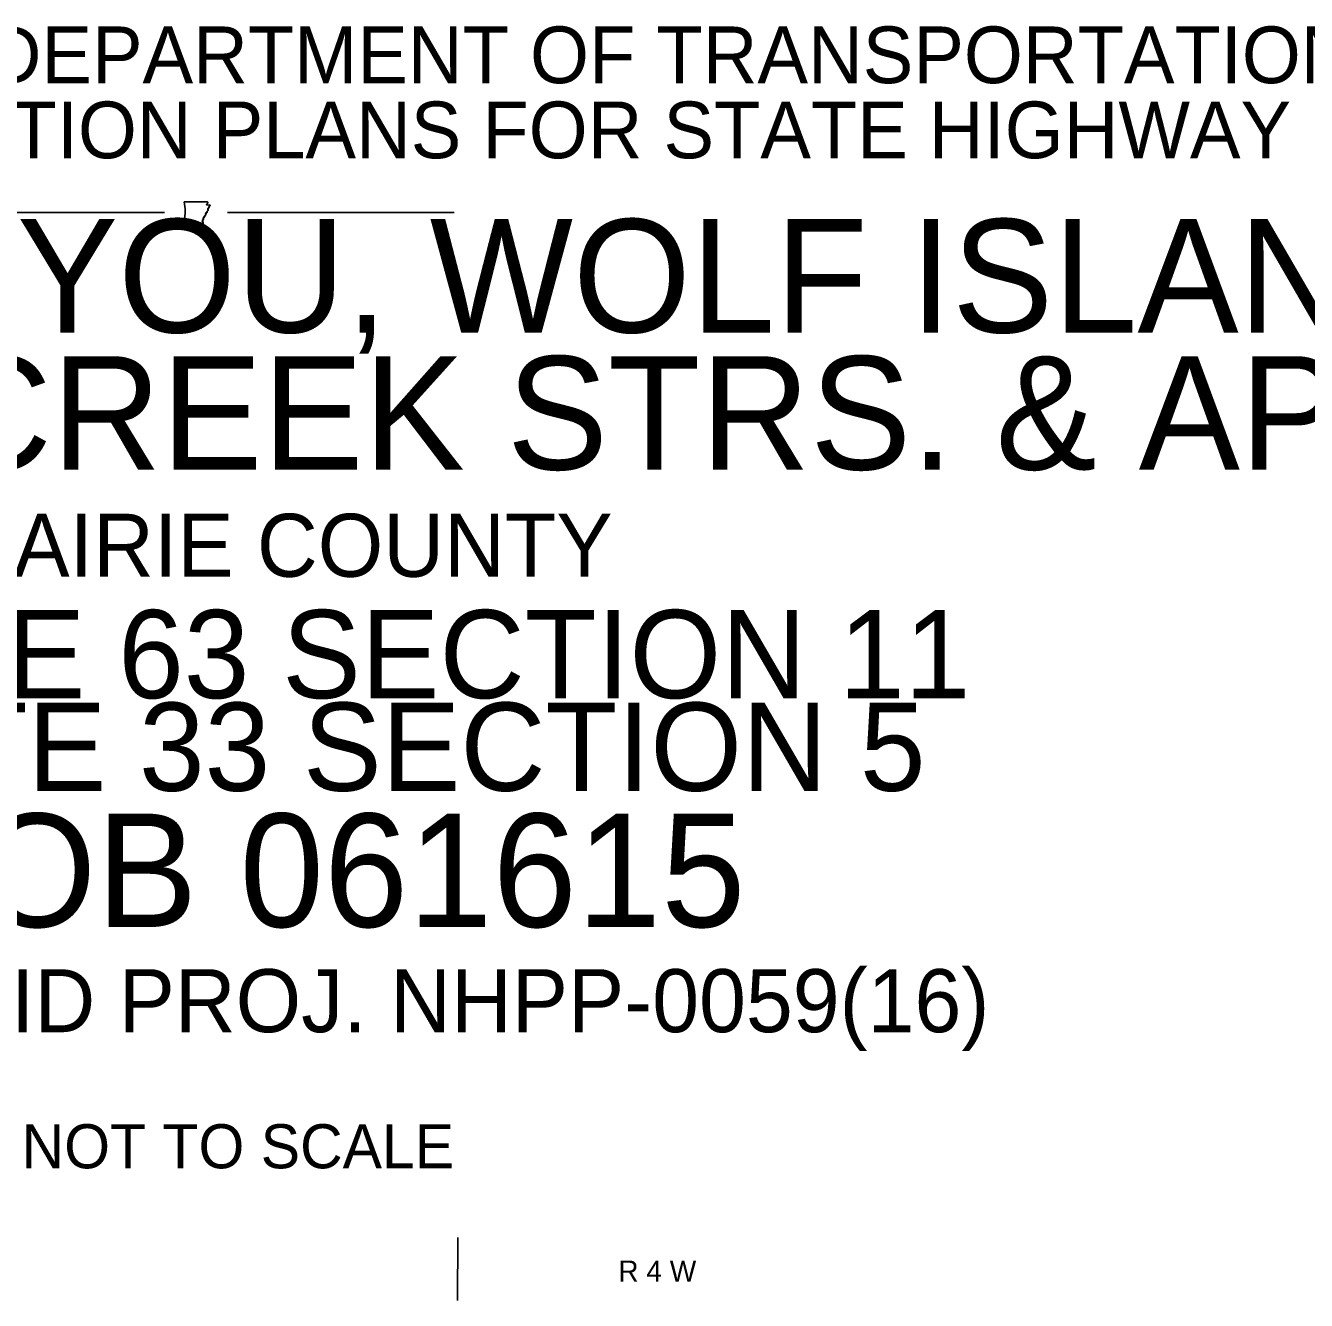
# Model space of a CAD drawing. Extents: x 982240 to 1103002, y 974866 to 1054902.
# Drawn here: x 1037189 to 1073786, y 1018200 to 1054617 of the extents above; entities that cross this region are included whole.
import ezdxf

# ---------------------------------------------------------------- set-up
doc = ezdxf.new("R2010")
doc.units = 0
doc.layers.add('R_Dimension', color=7, linetype='Continuous')
doc.layers.add('R_Draft', color=7, linetype='Continuous')

msp = doc.modelspace()

# ---------------------------------------------------------------- linework, layer by layer
at = {"layer": 'R_Dimension'}
msp.add_line((1049543, 1019999), (1049530, 1018200), dxfattribs=at)
at = {"layer": 'R_Draft'}
for p, q in [((1034676, 1049282), (1041156, 1049282)), ((1042956, 1049282), (1049436, 1049282))]:
    msp.add_line(p, q, dxfattribs=at)
for points in [[(1041720, 1049582), (1041917, 1049582), (1042089, 1049582), (1042293, 1049585), (1042387, 1049587)], [(1041735, 1049050), (1041745, 1049380), (1041720, 1049582)], [(1042358, 1049492), (1042450, 1049497)], [(1042247, 1048932), (1041802, 1048932), (1041802, 1049031)]]:
    msp.add_lwpolyline(points, dxfattribs=at)
for points in [[(1042350, 1049260), (1042347, 1049256), (1042343, 1049258), (1042343, 1049261), (1042343, 1049264), (1042342, 1049266), (1042339, 1049266), (1042339, 1049262), (1042339, 1049258), (1042338, 1049253), (1042340, 1049251), (1042344, 1049251), (1042347, 1049250), (1042348, 1049247), (1042348, 1049244), (1042347, 1049241), (1042345, 1049238), (1042342, 1049237), (1042339, 1049239), (1042339, 1049242), (1042337, 1049244), (1042335, 1049247), (1042333, 1049244), (1042333, 1049240), (1042333, 1049236), (1042333, 1049231), (1042336, 1049228), (1042338, 1049224), (1042337, 1049221), (1042335, 1049217), (1042334, 1049213), (1042333, 1049209), (1042333, 1049203), (1042332, 1049198), (1042331, 1049195), (1042327, 1049192), (1042325, 1049190), (1042324, 1049188), (1042323, 1049185), (1042322, 1049182), (1042320, 1049179), (1042318, 1049179), (1042317, 1049180), (1042316, 1049182), (1042316, 1049184), (1042315, 1049186), (1042312, 1049187), (1042310, 1049187), (1042309, 1049185), (1042310, 1049181), (1042311, 1049178), (1042310, 1049174), (1042310, 1049173), (1042306, 1049171), (1042303, 1049170), (1042300, 1049170), (1042297, 1049168), (1042296, 1049165), (1042294, 1049163), (1042292, 1049161), (1042290, 1049160), (1042287, 1049160), (1042284, 1049161), (1042282, 1049158), (1042282, 1049155), (1042285, 1049153), (1042288, 1049152), (1042292, 1049152), (1042295, 1049152), (1042298, 1049151), (1042297, 1049147), (1042294, 1049146), (1042290, 1049145), (1042286, 1049146), (1042282, 1049145), (1042280, 1049142), (1042281, 1049138), (1042286, 1049136), (1042288, 1049132), (1042288, 1049128), (1042286, 1049123), (1042284, 1049121), (1042280, 1049120), (1042277, 1049119), (1042276, 1049114), (1042275, 1049111), (1042272, 1049110), (1042269, 1049112), (1042266, 1049113), (1042264, 1049114), (1042260, 1049116), (1042258, 1049116), (1042258, 1049110), (1042259, 1049110), (1042262, 1049106), (1042265, 1049103), (1042266, 1049099)], [(1042402, 1049380), (1042403, 1049377), (1042401, 1049373), (1042400, 1049369), (1042400, 1049365), (1042396, 1049363), (1042393, 1049361), (1042395, 1049358), (1042399, 1049355), (1042402, 1049353), (1042405, 1049351), (1042405, 1049346), (1042406, 1049343), (1042407, 1049339), (1042408, 1049336), (1042405, 1049332), (1042403, 1049331), (1042400, 1049332), (1042397, 1049332), (1042394, 1049330), (1042393, 1049327), (1042391, 1049323), (1042389, 1049320), (1042388, 1049317), (1042385, 1049313), (1042382, 1049313), (1042378, 1049312), (1042376, 1049309), (1042376, 1049305), (1042378, 1049302), (1042380, 1049298), (1042381, 1049295), (1042381, 1049290), (1042379, 1049287), (1042377, 1049286), (1042376, 1049282), (1042374, 1049279), (1042373, 1049278), (1042370, 1049278), (1042367, 1049279), (1042364, 1049278), (1042362, 1049277), (1042359, 1049278), (1042356, 1049281), (1042354, 1049283), (1042352, 1049284), (1042349, 1049283), (1042349, 1049279), (1042350, 1049274), (1042351, 1049269), (1042350, 1049265), (1042350, 1049260)], [(1042387, 1049587), (1042387, 1049582), (1042389, 1049579), (1042389, 1049574), (1042391, 1049572), (1042395, 1049570), (1042398, 1049566), (1042399, 1049562), (1042398, 1049558), (1042398, 1049553), (1042397, 1049549), (1042396, 1049545), (1042394, 1049542), (1042391, 1049540), (1042388, 1049537), (1042386, 1049535), (1042383, 1049532), (1042380, 1049529), (1042378, 1049526), (1042375, 1049523), (1042374, 1049519), (1042371, 1049516), (1042369, 1049514), (1042366, 1049511), (1042364, 1049507), (1042362, 1049504), (1042361, 1049500), (1042359, 1049497), (1042359, 1049496)], [(1042449, 1049497), (1042450, 1049497), (1042454, 1049493), (1042456, 1049489), (1042459, 1049487), (1042462, 1049486), (1042464, 1049483), (1042465, 1049480), (1042465, 1049478), (1042461, 1049477), (1042457, 1049477), (1042454, 1049477), (1042451, 1049474), (1042454, 1049471), (1042457, 1049468), (1042458, 1049465), (1042456, 1049462), (1042452, 1049460), (1042448, 1049458), (1042445, 1049456), (1042444, 1049453), (1042440, 1049452), (1042436, 1049450), (1042432, 1049450), (1042429, 1049449), (1042425, 1049448), (1042423, 1049444), (1042424, 1049440), (1042424, 1049435), (1042428, 1049434), (1042431, 1049433), (1042435, 1049432), (1042434, 1049429), (1042432, 1049426), (1042429, 1049423), (1042426, 1049422), (1042423, 1049419), (1042424, 1049416), (1042426, 1049415), (1042428, 1049412), (1042428, 1049409), (1042425, 1049408), (1042422, 1049408), (1042419, 1049411), (1042417, 1049412), (1042414, 1049413), (1042412, 1049412), (1042412, 1049408), (1042411, 1049405), (1042412, 1049402), (1042413, 1049398), (1042413, 1049395), (1042412, 1049391), (1042410, 1049387), (1042407, 1049385), (1042406, 1049390), (1042406, 1049394), (1042404, 1049396), (1042402, 1049396), (1042400, 1049394), (1042397, 1049391), (1042393, 1049388), (1042391, 1049385), (1042392, 1049381), (1042395, 1049380), (1042397, 1049381), (1042398, 1049384), (1042400, 1049384), (1042402, 1049380)], [(1041802, 1049031), (1041802, 1049030), (1041800, 1049032), (1041797, 1049034), (1041793, 1049034), (1041789, 1049034), (1041785, 1049035), (1041781, 1049037), (1041777, 1049035), (1041772, 1049033), (1041770, 1049035), (1041766, 1049033), (1041764, 1049034), (1041759, 1049031), (1041755, 1049032), (1041753, 1049032), (1041749, 1049032), (1041748, 1049036), (1041745, 1049036), (1041742, 1049038), (1041740, 1049042), (1041738, 1049046), (1041735, 1049050)], [(1042266, 1049099), (1042265, 1049096), (1042263, 1049091), (1042264, 1049087), (1042266, 1049084), (1042268, 1049082), (1042272, 1049079), (1042271, 1049075), (1042270, 1049073), (1042265, 1049074), (1042262, 1049076), (1042259, 1049075), (1042255, 1049073), (1042253, 1049073), (1042253, 1049067), (1042257, 1049063), (1042260, 1049063), (1042264, 1049062), (1042265, 1049058), (1042263, 1049054), (1042259, 1049052), (1042254, 1049055), (1042251, 1049057), (1042248, 1049059), (1042244, 1049060), (1042241, 1049060), (1042240, 1049055), (1042242, 1049050), (1042245, 1049047), (1042248, 1049043), (1042248, 1049040), (1042246, 1049039), (1042242, 1049038), (1042240, 1049037), (1042239, 1049036), (1042240, 1049032), (1042241, 1049027), (1042241, 1049024), (1042240, 1049021), (1042238, 1049016), (1042238, 1049013), (1042240, 1049011), (1042241, 1049012), (1042244, 1049013), (1042245, 1049015), (1042247, 1049018), (1042249, 1049020), (1042252, 1049018), (1042253, 1049014), (1042251, 1049011), (1042249, 1049009), (1042246, 1049008), (1042243, 1049006), (1042244, 1049002), (1042246, 1049001), (1042250, 1049001), (1042253, 1049003), (1042255, 1049005), (1042257, 1049007), (1042258, 1049009), (1042260, 1049011), (1042262, 1049011), (1042264, 1049010), (1042263, 1049006), (1042262, 1049002), (1042259, 1048998), (1042257, 1048996), (1042254, 1048991), (1042254, 1048986), (1042255, 1048983), (1042257, 1048980), (1042260, 1048980), (1042263, 1048981), (1042265, 1048979), (1042265, 1048976), (1042263, 1048972), (1042260, 1048969), (1042259, 1048965), (1042260, 1048962), (1042260, 1048959), (1042259, 1048956), (1042257, 1048954), (1042252, 1048954), (1042248, 1048955), (1042245, 1048953), (1042246, 1048949), (1042248, 1048946), (1042250, 1048945), (1042253, 1048941), (1042254, 1048939), (1042254, 1048936), (1042252, 1048934), (1042247, 1048932)]]:
    msp.add_spline(points, degree=3, dxfattribs=at)

# ---------------------------------------------------------------- texts
for s, height, p in [('ARKANSAS DEPARTMENT OF TRANSPORTATION ', 1620, (1023676, 1052972)), ('CONSTRUCTION PLANS FOR STATE HIGHWAY', 1620, (1024483, 1050827)), ('LA GRUE BAYOU, WOLF ISLAND SLASH', 3240, (1010938, 1045849)), (' & HONEY CREEK STRS. & APPRS. (S)', 3240, (1012901, 1041933)), ('PRAIRIE COUNTY', 1800, (1033499, 1038871)), ('ROUTE 63 SECTION 11', 2520, (1027105, 1035402)), ('ROUTE 33 SECTION 5', 2520, (1027700, 1032756)), ('JOB 061615', 3240, (1033673, 1028866)), ('FED. AID PROJ. NHPP-0059(16)', 1800, (1029015, 1025861)), ('NOT TO SCALE', 1260, (1037075, 1021972)), ('R 4 W', 600, (1054124, 1018738))]:
    msp.add_text(s, height=height, dxfattribs=at).set_placement(p)

doc.saveas('drawing.dxf')
